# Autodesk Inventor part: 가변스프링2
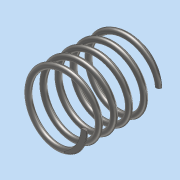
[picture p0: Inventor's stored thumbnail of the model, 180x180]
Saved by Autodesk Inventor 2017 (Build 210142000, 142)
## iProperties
Part Number: 가변스프링2
Material: 강철, 연강
Document SubType Name: Modeling
Designer: MRC
Density: 7.85 g/cm^3
Appearance: 반연마
Mass: 8.3874 g
Surface Area: 21.6623 cm^2
Volume: 1.06846 cm^3
Author: MRC
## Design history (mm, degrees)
sketch "스케치1"
  geometry: L1 (0, 0)-(0, 26.358); L2 (0, 0)-(11, 0); L3 (0, 26.358)-(11, 26.358); C1 r 1 at (11, 0)
  constraints: 6 end point, 2 horizontal, 1 centre point, 1 coincident, 1 vertical
  dimensions: "d0" = 11 distance of L1.start L2.end; "d1" = 11 distance of L1.end L3.end; "d2" = 2 diameter of C1; "d3" = 26.35829 distance of L1.start L1.end (derived)
feature "코일1" sketch "스케치1" pitch "d4" = 10; turns "d6" = 5; dims "d5" = 26.35829 (= d3), "d7" = 0, angle "d8" = 90 deg, angle "d9" = 90 deg, "d10" = 0, "d11" = 0
sketch "스케치2"
  geometry: L1 (26.358, 20)-(0, 20); L2 (0, 20)-(0, -20); L3 (0, -20)-(26.358, -20); L4 (26.358, -20)-(26.358, 20); 2 further points
  constraints: 8 end point, 2 parallel, 1 coincident, 1 horizontal, 1 midpoint, 1 perpendicular
  dimensions: "d13" = 26.35829 distance of L2.end L3.end (= d3); "d14" = 40 distance of L3.end L1.start
extrude "돌출1" sketch "스케치2" stored distance "d15" = 0; taper "d16" = 0 deg
node "솔리드1"
